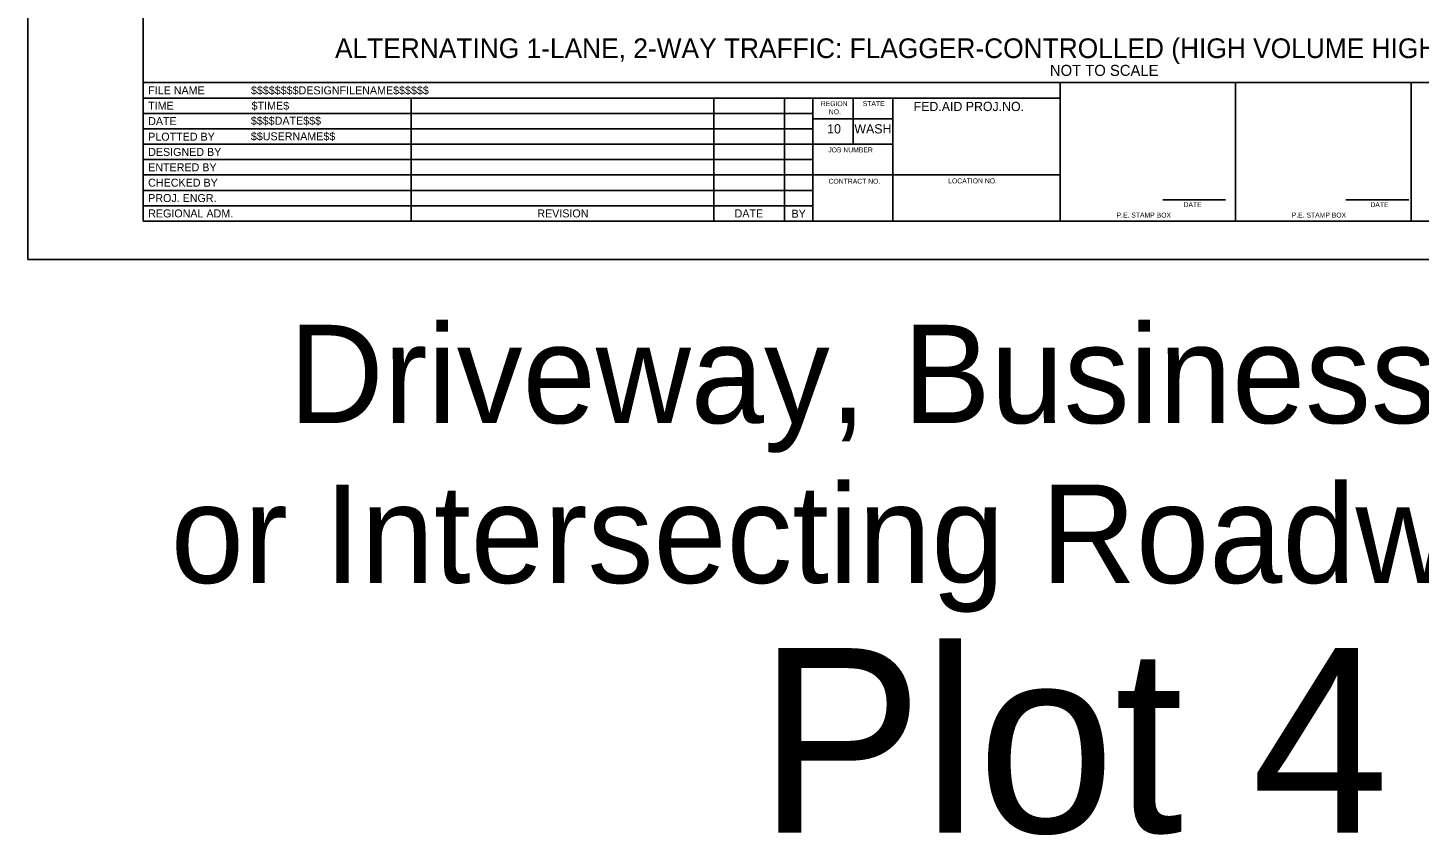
# Model space of a CAD drawing. Extents: x 99999.1 to 100095.7, y 99995 to 100010.7.
# Drawn here: x 100059.06 to 100070.38, y 99995.01 to 100001.57 of the extents above; entities that cross this region are included whole.
import ezdxf

# ---------------------------------------------------------------- set-up
doc = ezdxf.new("R2010")
doc.units = 0
for name, color, linetype in [('SH_DE_DetailHeading1Text', 7, 'Continuous'), ('SH_GI_PlotLimits', 7, 'Continuous'), ('SH_GI_SheetBorder', 7, 'Continuous'), ('SH_GI_SheetLocationText', 7, 'Continuous'), ('SH_GI_SheetTextInCells', 7, 'Continuous'), ('SH_GI_TitleBlockText', 7, 'Continuous')]:
    doc.layers.add(name, color=color, linetype=linetype)

msp = doc.modelspace()

# ---------------------------------------------------------------- linework, layer by layer
at = {"layer": 'SH_GI_PlotLimits'}
msp.add_lwpolyline([(100059.062, 99999.687), (100076.062, 99999.687), (100076.062, 100010.687), (100059.062, 100010.687)], close=True, dxfattribs=at)
at = {"layer": 'SH_GI_SheetBorder'}
for p, q in [((100060, 100010.375), (100060, 100000)), ((100060, 100001.126), (100075.75, 100001.126)), ((100067.457, 100000), (100067.457, 100001.126)), ((100068.883, 100000), (100068.883, 100001.126)), ((100070.309, 100001.126), (100070.309, 100000)), ((100060, 100001.001), (100067.457, 100001.001)), ((100062.179, 100001.001), (100062.179, 100000)), ((100064.641, 100001.001), (100064.641, 100000)), ((100065.216, 100001.001), (100065.216, 100000)), ((100065.445, 100001.001), (100065.445, 100000)), ((100065.772, 100000.625), (100065.772, 100001.001)), ((100066.096, 100000), (100066.096, 100001.001)), ((100060, 100000.876), (100062.182, 100000.876)), ((100062.182, 100000.876), (100065.447, 100000.876)), ((100066.096, 100000.831), (100065.447, 100000.831)), ((100060, 100000.751), (100062.182, 100000.751)), ((100062.182, 100000.751), (100065.447, 100000.751)), ((100060, 100000.625), (100065.447, 100000.625)), ((100066.096, 100000.625), (100065.447, 100000.625)), ((100060, 100000.5), (100065.447, 100000.5)), ((100060, 100000.375), (100065.447, 100000.375)), ((100067.457, 100000.375), (100065.447, 100000.375)), ((100060, 100000.25), (100065.447, 100000.25)), ((100060, 100000.125), (100065.447, 100000.125)), ((100068.29, 100000.173), (100068.802, 100000.173)), ((100069.78, 100000.173), (100070.291, 100000.173)), ((100060, 100000), (100075.75, 100000))]:
    msp.add_line(p, q, dxfattribs=at)

# ---------------------------------------------------------------- texts
at = {"layer": 'SH_DE_DetailHeading1Text'}
for s, height, p in [('ALTERNATING 1-LANE, 2-WAY TRAFFIC: FLAGGER-CONTROLLED (HIGH VOLUME HIGHWAYS, 40 MPH OR LESS)', 0.16, (100061.56, 100001.326)), ('NOT TO SCALE', 0.09, (100067.373, 100001.181))]:
    msp.add_text(s, height=height, rotation=360, dxfattribs=at).set_placement(p)
at = {"layer": 'SH_GI_SheetLocationText'}
for s, height, p in [('Driveway, Business Access,', 0.8, (100061.184, 99998.357)), ('or Intersecting Roadway Details', 0.8, (100060.225, 99997.057)), ('Plot 4', 1.5, (100065.001, 99995.027))]:
    msp.add_text(s, height=height, dxfattribs=at).set_placement(p)
at = {"layer": 'SH_GI_SheetTextInCells'}
for s, height, p in [('FILE NAME', 0.0651, (100060.041, 100001.031)), ('TIME', 0.0651, (100060.041, 100000.906)), ('REGION', 0.04, (100065.51, 100000.935)), ('NO.', 0.04, (100065.575, 100000.869)), ('STATE', 0.04, (100065.851, 100000.936)), ('FED.AID PROJ.NO.', 0.07506, (100066.265, 100000.895)), ('DATE', 0.0651, (100060.041, 100000.781)), ('10', 0.0751, (100065.562, 100000.713)), ('WASH', 0.0751, (100065.783, 100000.713)), ('PLOTTED BY', 0.0651, (100060.041, 100000.654)), ('DESIGNED BY', 0.06505, (100060.041, 100000.53)), ('JOB NUMBER', 0.04, (100065.571, 100000.559)), ('ENTERED BY', 0.0651, (100060.041, 100000.405)), ('CHECKED BY', 0.0651, (100060.041, 100000.28)), ('CONTRACT NO.', 0.04003, (100065.573, 100000.304)), ('LOCATION NO.', 0.04003, (100066.546, 100000.307)), ('PROJ. ENGR.', 0.06505, (100060.041, 100000.155)), ('REGIONAL ADM.', 0.06505, (100060.041, 100000.03)), ('REVISION', 0.0651, (100063.205, 100000.03)), ('DATE', 0.04, (100068.46, 100000.114)), ('DATE', 0.04, (100069.979, 100000.114)), ('DATE', 0.0651, (100064.809, 100000.03)), ('BY', 0.0651, (100065.272, 100000.028)), ('P.E. STAMP BOX', 0.04003, (100067.915, 100000.029)), ('P.E. STAMP BOX', 0.04003, (100069.339, 100000.029))]:
    msp.add_text(s, height=height, dxfattribs=at).set_placement(p)
at = {"layer": 'SH_GI_TitleBlockText'}
for s, height, p in [('$$$$$$$$DESIGNFILENAME$$$$$$', 0.06505, (100060.877, 100001.031)), ('$TIME$', 0.0651, (100060.882, 100000.906)), ('$$$$DATE$$$', 0.06505, (100060.876, 100000.784)), ('$$USERNAME$$', 0.06505, (100060.876, 100000.657))]:
    msp.add_text(s, height=height, dxfattribs=at).set_placement(p)

doc.saveas('drawing.dxf')
